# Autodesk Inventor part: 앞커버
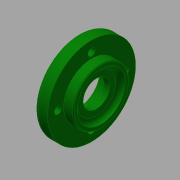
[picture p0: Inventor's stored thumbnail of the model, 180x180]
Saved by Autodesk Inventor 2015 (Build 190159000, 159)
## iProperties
Created: 2015-12
Part Number: 앞커버
Material: 일반
Document SubType Name: Modeling
Designer: mduedu
Density: 1 g/cm^3
Appearance: 진녹색
Author: mduedu
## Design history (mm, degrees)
sketch "스케치1"
  geometry: L1 (0, 0)-(14, 0); L2 (14, 0)-(14, 17.5); L3 (14, 17.5)-(8, 17.5); L4 (8, 17.5)-(8, 27.5); L5 (8, 27.5)-(0, 27.5); L6 (0, 27.5)-(0, 0)
  constraints: 12 end point, 4 parallel, 1 horizontal, 1 perpendicular
  dimensions: "d0" = 14 distance between parallel lines of L2 L6; "d2" = 8 distance of L4.end L5.end; "d3" = 55 diameter of L5 L1; "d4" = 35 diameter of L3 L1
revolve "회전1" sketch "스케치1" stored, may be unused: angle "d5" = 90 deg
hole "구멍1" diameter "d8" = 30; stored, may be unused: countersink angle "d12" = 90 deg, drill point angle "d14" = 0 deg; dims "d6" = 10, "d7" = 10, "d9" = 6, "d10" = 4, "d11" = 2, "d13" = 3
hole "구멍2" diameter "d17" = 25; stored, may be unused: countersink angle "d21" = 90 deg, drill point angle "d23" = 0 deg; dims "d15" = 10, "d16" = 10, "d18" = 6, "d19" = 4, "d20" = 2, "d22" = 7.3
hole "구멍3" diameter "d26" = 16.5; stored, may be unused: countersink angle "d30" = 90 deg, drill point angle "d32" = 0 deg; dims "d24" = 10, "d25" = 10, "d27" = 6, "d28" = 4, "d29" = 2, "d31" = 7.3
fillet "모깎기1" dims "d33" = 0.3
chamfer "모따기1" distance "d34" = 1; stored, may be unused: second distance "d35" = 2, angle "d36" = 30 deg
fillet "모깎기2" dims "d37" = 3
fillet "모깎기3" dims "d38" = 2
chamfer "모따기2" distance "d39" = 0.5; stored, may be unused: second distance "d40" = 2, angle "d41" = 45 deg
sketch "스케치2" dims "d42" = 42
  geometry: 9 further points
  constraints: 3 coincident, 2 vertical alignment, 9 other
  dimensions: "d46" = 360 deg dimension on point (0, 0) point (0, 21) (derived)
sketch "스케치3"
  geometry: 4 further points
hole "구멍4" sketch "스케치3" at (-21, 0), (0, -21), (21, 0), (0, 21) diameter "d50" = 4.5; stored, may be unused: countersink angle "d54" = 90 deg, drill point angle "d56" = 0 deg; dims "d51" = 6, "d52" = 8, "d53" = 4.6, "d55" = 8
node "솔리드1"
